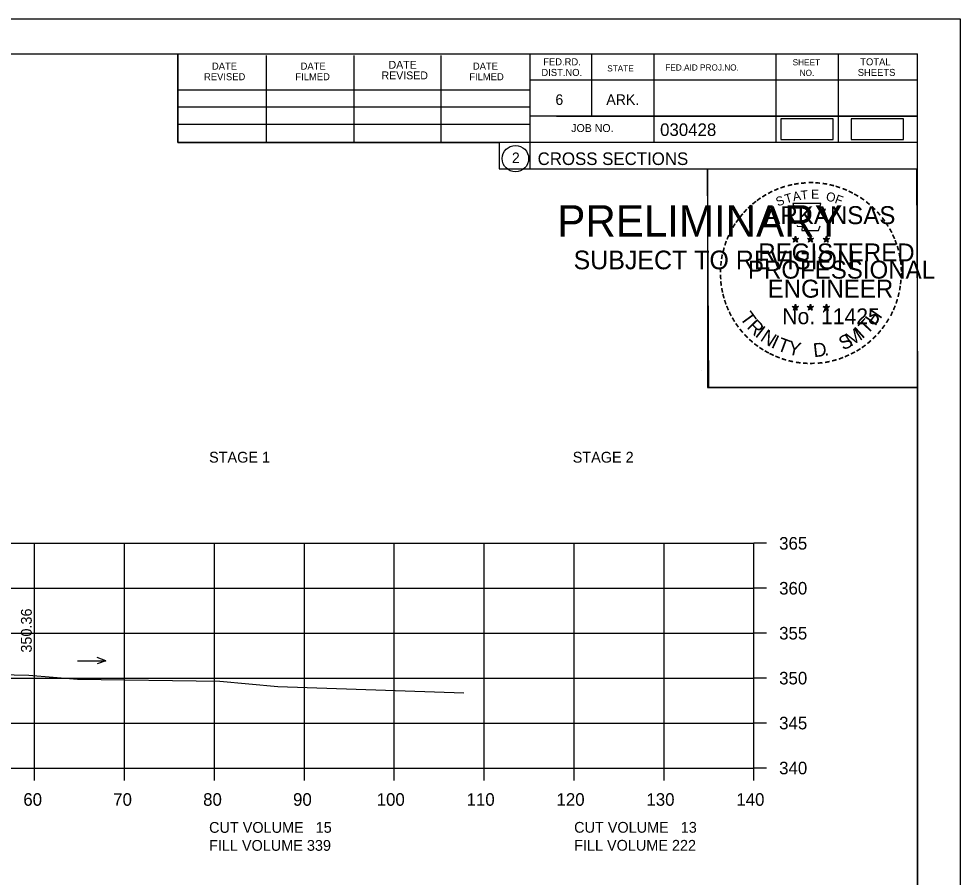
# Model space of a CAD drawing. Extents: x 1374859 to 1376773, y 382242 to 389804.
# Drawn here: x 1376192.8 to 1376297.5, y 382359.6 to 382455.1 of the extents above; entities that cross this region are included whole.
import ezdxf

# ---------------------------------------------------------------- set-up
doc = ezdxf.new("R2010")
doc.units = 0
for name, color, linetype in [('R_Axis', 7, 'Continuous'), ('R_Axis Annot', 7, 'Continuous'), ('R_Border', 7, 'Continuous'), ('R_Border PE', 7, 'Continuous'), ('R_Border Prem', 7, 'Continuous'), ('R_Exist Surface', 7, 'Continuous'), ('R_Grid', 7, 'Continuous'), ('R_MOT', 7, 'Continuous'), ('R_No Plot', 7, 'Continuous'), ('R_Water Annot', 7, 'Continuous'), ('R_Xsect Elev', 7, 'Continuous')]:
    doc.layers.add(name, color=color, linetype=linetype)

msp = doc.modelspace()

# ---------------------------------------------------------------- linework, layer by layer
at = {"layer": 'R_Axis'}
for p, q in [((1376274.57, 382371.72), (1376274.57, 382396.72)), ((1376275.97, 382396.72), (1376274.57, 382396.72)), ((1376275.97, 382391.72), (1376274.57, 382391.72)), ((1376275.97, 382386.72), (1376274.57, 382386.72)), ((1376275.97, 382381.72), (1376274.57, 382381.72)), ((1376275.97, 382376.72), (1376274.57, 382376.72)), ((1375994.57, 382371.72), (1376274.57, 382371.72)), ((1376194.57, 382370.32), (1376194.57, 382371.72)), ((1376204.57, 382370.32), (1376204.57, 382371.72)), ((1376214.57, 382370.32), (1376214.57, 382371.72)), ((1376224.57, 382370.32), (1376224.57, 382371.72)), ((1376234.57, 382370.32), (1376234.57, 382371.72)), ((1376244.57, 382370.32), (1376244.57, 382371.72)), ((1376254.57, 382370.32), (1376254.57, 382371.72)), ((1376264.57, 382370.32), (1376264.57, 382371.72)), ((1376274.57, 382370.32), (1376274.57, 382371.72)), ((1376275.97, 382371.72), (1376274.57, 382371.72))]:
    msp.add_line(p, q, dxfattribs=at)
at = {"layer": 'R_Border'}
for p, q in [((1375976.57, 382451.18), (1376292.75, 382451.18)), ((1376210.49, 382441.3), (1376210.49, 382451.18)), ((1376249.65, 382451.18), (1376249.65, 382438.38)), ((1376256.49, 382451.18), (1376256.49, 382444.24)), ((1376263.43, 382451.18), (1376263.43, 382441.3)), ((1376277.01, 382451.18), (1376277.01, 382441.3)), ((1376283.95, 382451.18), (1376283.95, 382441.3)), ((1376292.75, 382245.72), (1376292.75, 382451.18)), ((1376220.35, 382441.3), (1376220.35, 382450.98)), ((1376230.11, 382441.3), (1376230.11, 382450.98)), ((1376239.79, 382441.3), (1376239.79, 382450.98)), ((1376292.75, 382448.24), (1376249.65, 382448.24)), ((1376292.75, 382448.26), (1376292.75, 382448.26)), ((1376210.49, 382447.16), (1376249.65, 382447.16)), ((1376210.49, 382445.3), (1376249.65, 382445.3)), ((1376292.75, 382444.24), (1376249.65, 382444.24)), ((1376252.61, 382444.24), (1376292.75, 382444.24)), ((1376210.49, 382441.3), (1376210.49, 382443.36)), ((1376210.49, 382443.36), (1376249.65, 382443.36)), ((1376292.75, 382441.3), (1376210.49, 382441.3)), ((1376249.65, 382438.38), (1376292.75, 382438.38))]:
    msp.add_line(p, q, dxfattribs=at)
msp.add_circle((1376248.04, 382439.52), 1.47, dxfattribs=at)
at = {"layer": 'R_Border PE'}
for p, q in [((1376278.84, 382430.64), (1376279.18, 382430.52)), ((1376278.84, 382430.64), (1376279.09, 382430.59)), ((1376278.84, 382430.64), (1376279.07, 382430.51)), ((1376278.97, 382430.23), (1376279.18, 382430.52)), ((1376278.97, 382430.23), (1376279.09, 382430.47)), ((1376278.97, 382430.23), (1376279.18, 382430.44)), ((1376279.18, 382430.89), (1376279.14, 382430.64)), ((1376279.18, 382430.52), (1376279.18, 382430.89)), ((1376279.18, 382430.89), (1376279.23, 382430.64)), ((1376279.53, 382430.64), (1376279.18, 382430.52)), ((1376279.4, 382430.23), (1376279.18, 382430.52)), ((1376279.4, 382430.23), (1376279.18, 382430.44)), ((1376279.53, 382430.64), (1376279.25, 382430.59)), ((1376279.4, 382430.23), (1376279.26, 382430.52)), ((1376279.53, 382430.64), (1376279.33, 382430.53)), ((1376280.51, 382430.64), (1376280.85, 382430.52)), ((1376280.51, 382430.64), (1376280.76, 382430.59)), ((1376280.51, 382430.64), (1376280.74, 382430.51)), ((1376280.64, 382430.23), (1376280.85, 382430.52)), ((1376280.64, 382430.23), (1376280.76, 382430.47)), ((1376280.64, 382430.23), (1376280.85, 382430.44)), ((1376280.85, 382430.89), (1376280.81, 382430.64)), ((1376280.85, 382430.52), (1376280.85, 382430.89)), ((1376280.85, 382430.89), (1376280.9, 382430.64)), ((1376281.2, 382430.64), (1376280.85, 382430.52)), ((1376281.07, 382430.23), (1376280.85, 382430.52)), ((1376281.07, 382430.23), (1376280.85, 382430.44)), ((1376281.2, 382430.64), (1376280.92, 382430.59)), ((1376281.07, 382430.23), (1376280.93, 382430.52)), ((1376281.2, 382430.64), (1376281, 382430.53)), ((1376282.27, 382430.62), (1376282.62, 382430.51)), ((1376282.27, 382430.62), (1376282.52, 382430.58)), ((1376282.27, 382430.62), (1376282.51, 382430.5)), ((1376282.4, 382430.22), (1376282.62, 382430.51)), ((1376282.4, 382430.22), (1376282.53, 382430.46)), ((1376282.4, 382430.22), (1376282.62, 382430.43)), ((1376282.62, 382430.88), (1376282.58, 382430.63)), ((1376282.62, 382430.51), (1376282.62, 382430.88)), ((1376282.62, 382430.88), (1376282.67, 382430.63)), ((1376282.97, 382430.62), (1376282.62, 382430.51)), ((1376282.83, 382430.22), (1376282.62, 382430.51)), ((1376282.83, 382430.22), (1376282.62, 382430.43)), ((1376282.97, 382430.62), (1376282.68, 382430.57)), ((1376282.83, 382430.22), (1376282.69, 382430.51)), ((1376282.97, 382430.62), (1376282.76, 382430.52)), ((1376278.83, 382423.06), (1376279.18, 382422.95)), ((1376278.83, 382423.06), (1376279.08, 382423.02)), ((1376278.83, 382423.06), (1376279.07, 382422.94)), ((1376278.96, 382422.65), (1376279.18, 382422.95)), ((1376278.96, 382422.65), (1376279.09, 382422.9)), ((1376278.96, 382422.65), (1376279.18, 382422.87)), ((1376279.18, 382423.32), (1376279.14, 382423.06)), ((1376279.18, 382422.95), (1376279.18, 382423.32)), ((1376279.18, 382423.32), (1376279.23, 382423.07)), ((1376279.53, 382423.06), (1376279.18, 382422.95)), ((1376279.39, 382422.65), (1376279.18, 382422.95)), ((1376279.39, 382422.65), (1376279.18, 382422.87)), ((1376279.53, 382423.06), (1376279.24, 382423.01)), ((1376279.39, 382422.65), (1376279.26, 382422.95)), ((1376279.53, 382423.06), (1376279.32, 382422.96)), ((1376280.5, 382423.06), (1376280.85, 382422.95)), ((1376280.5, 382423.06), (1376280.75, 382423.02)), ((1376280.5, 382423.06), (1376280.74, 382422.94)), ((1376280.63, 382422.65), (1376280.85, 382422.95)), ((1376280.63, 382422.65), (1376280.76, 382422.9)), ((1376280.63, 382422.65), (1376280.85, 382422.87)), ((1376280.85, 382423.32), (1376280.81, 382423.06)), ((1376280.85, 382422.95), (1376280.85, 382423.32)), ((1376280.85, 382423.32), (1376280.9, 382423.07)), ((1376281.2, 382423.06), (1376280.85, 382422.95)), ((1376281.06, 382422.65), (1376280.85, 382422.95)), ((1376281.06, 382422.65), (1376280.85, 382422.87)), ((1376281.2, 382423.06), (1376280.91, 382423.01)), ((1376281.06, 382422.65), (1376280.93, 382422.95)), ((1376281.2, 382423.06), (1376280.99, 382422.96)), ((1376282.27, 382423.05), (1376282.62, 382422.94)), ((1376282.27, 382423.05), (1376282.52, 382423.01)), ((1376282.27, 382423.05), (1376282.5, 382422.93)), ((1376282.4, 382422.64), (1376282.62, 382422.94)), ((1376282.4, 382422.64), (1376282.53, 382422.89)), ((1376282.4, 382422.64), (1376282.61, 382422.86)), ((1376282.62, 382423.31), (1376282.58, 382423.05)), ((1376282.83, 382422.64), (1376282.61, 382422.86)), ((1376282.62, 382422.94), (1376282.62, 382423.31)), ((1376282.62, 382423.31), (1376282.67, 382423.06)), ((1376282.96, 382423.05), (1376282.62, 382422.94)), ((1376282.83, 382422.64), (1376282.62, 382422.94)), ((1376282.96, 382423.05), (1376282.68, 382423)), ((1376282.83, 382422.64), (1376282.69, 382422.94)), ((1376282.96, 382423.05), (1376282.76, 382422.95))]:
    msp.add_line(p, q, dxfattribs=at)
for points in [[(1376278.88, 382434.51), (1376279.15, 382433.69)], [(1376282.39, 382433.59), (1376282.53, 382433.88), (1376281.84, 382433.85), (1376281.99, 382434.51), (1376278.88, 382434.51)], [(1376279.37, 382432.09), (1376279.37, 382432), (1376279.93, 382431.98), (1376279.88, 382431.51), (1376281.75, 382431.51), (1376281.95, 382432.05)], [(1376279.18, 382430.89), (1376279.4, 382430.23), (1376278.84, 382430.64), (1376279.53, 382430.64), (1376278.97, 382430.23), (1376279.18, 382430.89)], [(1376280.85, 382430.89), (1376281.07, 382430.23), (1376280.51, 382430.64), (1376281.2, 382430.64), (1376280.64, 382430.23), (1376280.85, 382430.89)], [(1376282.62, 382430.88), (1376282.83, 382430.22), (1376282.27, 382430.62), (1376282.97, 382430.62), (1376282.4, 382430.22), (1376282.62, 382430.88)], [(1376279.18, 382423.32), (1376279.39, 382422.65), (1376278.83, 382423.06), (1376279.53, 382423.06), (1376278.96, 382422.65), (1376279.18, 382423.32)], [(1376280.85, 382423.32), (1376281.06, 382422.65), (1376280.5, 382423.06), (1376281.2, 382423.06), (1376280.63, 382422.65), (1376280.85, 382423.32)], [(1376282.62, 382423.31), (1376282.83, 382422.64), (1376282.27, 382423.05), (1376282.96, 382423.05), (1376282.4, 382422.64), (1376282.62, 382423.31)]]:
    msp.add_lwpolyline(points, dxfattribs=at)
for centre, radius in [((1376279.18, 382430.52), 0.172), ((1376279.18, 382430.52), 0.145), ((1376279.18, 382430.52), 0.116), ((1376279.18, 382430.52), 0.0991), ((1376279.18, 382430.52), 0.0747), ((1376279.18, 382430.52), 0.0495), ((1376279.18, 382430.52), 0.0296), ((1376280.85, 382430.52), 0.172), ((1376280.85, 382430.52), 0.145), ((1376280.85, 382430.52), 0.116), ((1376280.85, 382430.52), 0.0991), ((1376280.85, 382430.52), 0.0747), ((1376280.85, 382430.52), 0.0495), ((1376280.85, 382430.52), 0.0296), ((1376282.62, 382430.51), 0.172), ((1376282.62, 382430.51), 0.145), ((1376282.62, 382430.51), 0.116), ((1376282.62, 382430.51), 0.0991), ((1376282.62, 382430.51), 0.0747), ((1376282.62, 382430.51), 0.0495), ((1376282.62, 382430.51), 0.0296), ((1376279.18, 382422.95), 0.172), ((1376279.18, 382422.95), 0.145), ((1376279.18, 382422.95), 0.116), ((1376279.18, 382422.95), 0.0991), ((1376279.18, 382422.95), 0.0747), ((1376279.18, 382422.95), 0.0495), ((1376279.18, 382422.95), 0.0296), ((1376280.85, 382422.95), 0.172), ((1376280.85, 382422.95), 0.145), ((1376280.85, 382422.95), 0.116), ((1376280.85, 382422.95), 0.0991), ((1376280.85, 382422.95), 0.0747), ((1376280.85, 382422.95), 0.0495), ((1376280.85, 382422.95), 0.0296), ((1376282.62, 382422.94), 0.172), ((1376282.62, 382422.94), 0.145), ((1376282.62, 382422.94), 0.116), ((1376282.62, 382422.94), 0.0991), ((1376282.62, 382422.94), 0.0747), ((1376282.62, 382422.94), 0.0495), ((1376282.62, 382422.94), 0.0296)]:
    msp.add_circle(centre, radius, dxfattribs=at)
at = {"layer": 'R_Exist Surface'}
msp.add_lwpolyline([(1376074.07, 382383.65), (1376082.2, 382383.68), (1376083.35, 382383.71), (1376093.58, 382383.15), (1376102.46, 382386.11), (1376105.38, 382387.13), (1376115.82, 382390.6), (1376117.69, 382390.67), (1376123.23, 382390.89), (1376129.54, 382391.04), (1376135.35, 382391.19), (1376141.62, 382391), (1376147.42, 382390.82), (1376152.27, 382390.54), (1376157.14, 382390.2), (1376162.27, 382388.39), (1376169.25, 382385.85), (1376180.89, 382382.3), (1376184.16, 382382.26), (1376193.92, 382382.05), (1376199.35, 382381.62), (1376215.18, 382381.38), (1376221.62, 382380.78), (1376242.32, 382380.08)], dxfattribs=at)
at = {"layer": 'R_Grid'}
for p, q in [((1375994.57, 382396.72), (1376274.57, 382396.72)), ((1376194.57, 382371.72), (1376194.57, 382396.72)), ((1376204.57, 382371.72), (1376204.57, 382396.72)), ((1376214.57, 382371.72), (1376214.57, 382396.72)), ((1376224.57, 382371.72), (1376224.57, 382396.72)), ((1376234.57, 382371.72), (1376234.57, 382396.72)), ((1376244.57, 382371.72), (1376244.57, 382396.72)), ((1376254.57, 382371.72), (1376254.57, 382396.72)), ((1376264.57, 382371.72), (1376264.57, 382396.72)), ((1376274.57, 382371.72), (1376274.57, 382396.72)), ((1375994.57, 382391.72), (1376274.57, 382391.72)), ((1375994.57, 382386.72), (1376274.57, 382386.72)), ((1375994.57, 382381.72), (1376274.57, 382381.72)), ((1375994.57, 382376.72), (1376274.57, 382376.72)), ((1375994.57, 382371.72), (1376274.57, 382371.72))]:
    msp.add_line(p, q, dxfattribs=at)
at = {"layer": 'R_MOT'}
for points in [[(1376277.55, 382441.65), (1376283.38, 382441.65), (1376283.38, 382443.96), (1376277.55, 382443.96)], [(1376285.38, 382441.65), (1376291.21, 382441.65), (1376291.21, 382443.96), (1376285.38, 382443.96)]]:
    msp.add_lwpolyline(points, close=True, dxfattribs=at)
at = {"layer": 'R_No Plot'}
for p, q in [((1375964.17, 382455.07), (1376297.5, 382455.07)), ((1376268.78, 382415.92), (1376268.78, 382415.92))]:
    msp.add_line(p, q, dxfattribs=at)
for points in [[(1375964.16, 382455.07), (1376297.5, 382455.07), (1376297.5, 382241.74), (1375964.16, 382241.74)], [(1376210.49, 382451.18), (1376210.49, 382441.3), (1376246.22, 382441.3), (1376246.22, 382438.38), (1376269.42, 382438.38), (1376269.42, 382414.05), (1376292.75, 382414.05), (1376292.75, 382245.72), (1375976.57, 382245.72), (1375976.57, 382451.18)], [(1376269.42, 382438.38), (1376292.63, 382438.38), (1376292.75, 382414.05), (1376269.54, 382414.05)]]:
    msp.add_lwpolyline(points, close=True, dxfattribs=at)
at = {"layer": 'R_Water Annot'}
for p, q in [((1376199.35, 382383.65), (1376202.49, 382383.65)), ((1376202.49, 382383.65), (1376201.53, 382384)), ((1376202.49, 382383.65), (1376201.53, 382383.3))]:
    msp.add_line(p, q, dxfattribs=at)

# ---------------------------------------------------------------- texts
at = {"layer": 'R_Axis Annot'}
for s, p in [('STAGE 1', (1376213.97, 382405.7)), ('STAGE 2', (1376254.41, 382405.7))]:
    msp.add_text(s, height=1.2, rotation=360, dxfattribs=at).set_placement(p)
for s, height, p in [('365', 1.4, (1376277.37, 382396.02)), ('360', 1.4, (1376277.37, 382391.02)), ('355', 1.4, (1376277.37, 382386.02)), ('350', 1.4, (1376277.37, 382381.02)), ('345', 1.4, (1376277.37, 382376.02)), ('340', 1.4, (1376277.37, 382371.02)), ('60', 1.4, (1376193.31, 382367.52)), ('70', 1.4, (1376203.31, 382367.52)), ('80', 1.4, (1376213.31, 382367.52)), ('90', 1.4, (1376223.31, 382367.52)), ('100', 1.4, (1376232.61, 382367.52)), ('110', 1.4, (1376242.61, 382367.52)), ('120', 1.4, (1376252.61, 382367.52)), ('130', 1.4, (1376262.61, 382367.52)), ('140', 1.4, (1376272.61, 382367.52)), ('CUT VOLUME   15', 1.2, (1376213.97, 382364.51)), ('CUT VOLUME   13', 1.2, (1376254.57, 382364.52)), ('FILL VOLUME 339', 1.2, (1376213.97, 382362.51)), ('FILL VOLUME 222', 1.2, (1376254.57, 382362.52))]:
    msp.add_text(s, height=height, dxfattribs=at).set_placement(p)
at = {"layer": 'R_Border'}
for s, height, p in [('DATE', 0.782, (1376214.29, 382449.42)), ('DATE', 0.782, (1376224.15, 382449.42)), ('DATE', 0.879, (1376233.93, 382449.52)), ('DATE', 0.782, (1376243.31, 382449.42)), ('FED.RD.', 0.782, (1376251.13, 382449.9)), ('SHEET', 0.684, (1376278.87, 382449.9)), ('TOTAL', 0.782, (1376286.39, 382449.9)), ('REVISED', 0.782, (1376213.41, 382448.24)), ('FILMED', 0.782, (1376223.57, 382448.24)), ('REVISED', 0.879, (1376233.15, 382448.34)), ('FILMED', 0.782, (1376242.91, 382448.24)), ('DIST.NO.', 0.782, (1376250.93, 382448.72)), ('STATE', 0.684, (1376258.25, 382449.22)), ('FED.AID PROJ.NO.', 0.684, (1376264.71, 382449.32)), ('NO.', 0.684, (1376279.65, 382448.72)), ('SHEETS', 0.782, (1376286.11, 382448.72)), ('6', 1.17, (1376252.49, 382445.5)), ('ARK.', 1.172, (1376258.15, 382445.5)), ('JOB NO.', 0.879, (1376254.25, 382442.48)), ('030428', 1.4, (1376264.13, 382442.04)), ('2', 1.17, (1376247.65, 382439.03)), ('CROSS SECTIONS', 1.4, (1376250.51, 382438.81))]:
    msp.add_text(s, height=height, rotation=360, dxfattribs=at).set_placement(p)
at = {"layer": 'R_Border PE'}
for s, height, rotation, p in [('-', 1.6, 19.1761, (1376277.62, 382435.64)), ('-', 1.6, 13.6301, (1376278.37, 382435.88)), ('-', 1.6, 10.2193, (1376279.05, 382436.04)), ('-', 1.6, 5.8968, (1376279.78, 382436.15)), ('-', 1.6, 0.1862, (1376280.55, 382436.23)), ('-', 1.6, 357.743, (1376281.28, 382436.21)), ('-', 1.6, 352.1617, (1376282.02, 382436.16)), ('-', 1.6, 347.2049, (1376282.74, 382436.04)), ('-', 1.6, 342.3362, (1376283.37, 382435.89)), ('-', 1.6, 34.0636, (1376275.76, 382434.68)), ('-', 1.6, 28.7918, (1376276.36, 382435.05)), ('-', 1.6, 24.3072, (1376276.99, 382435.37)), ('T', 1, 16.4036, (1376278.15, 382434.52)), ('A', 1, 11.2132, (1376278.97, 382434.77)), ('T', 1, 6.0228, (1376279.82, 382434.94)), ('E', 1, 0.8323, (1376280.93, 382435.05)), ('O', 1, 350.4515, (1376282.53, 382434.84)), ('F', 1, 340.0707, (1376283.48, 382434.61)), ('-', 1.6, 337.8551, (1376284.11, 382435.66)), ('-', 1.6, 334.1211, (1376284.74, 382435.39)), ('-', 1.6, 329.6409, (1376285.32, 382435.11)), ('-', 1.6, 42.9622, (1376274.27, 382433.49)), ('-', 1.6, 38.9507, (1376274.71, 382433.91)), ('-', 1.6, 36.2317, (1376275.18, 382434.29)), ('S', 1, 21.594, (1376277.23, 382434.19)), ('-', 1.6, 325.8627, (1376285.96, 382434.75)), ('-', 1.6, 320.5297, (1376286.57, 382434.32)), ('-', 1.6, 50.6142, (1376273.42, 382432.53)), ('-', 1.6, 48.423, (1376273.83, 382433.02)), ('ARKANSAS', 2, 360, (1376275.73, 382432.23)), ('-', 1.6, 315.5786, (1376287.17, 382433.84)), ('-', 1.6, 309.8797, (1376287.74, 382433.29)), ('-', 1.6, 58.0706, (1376272.68, 382431.44)), ('-', 1.6, 54.2325, (1376273.01, 382431.96)), ('-', 1.6, 306.6522, (1376288.27, 382432.68)), ('-', 1.4, 303.6753, (1376288.75, 382432.12)), ('-', 1.6, 62.8713, (1376272.37, 382430.82)), ('-', 1.6, 299.6684, (1376289.07, 382431.51)), ('-', 1.6, 72.3945, (1376271.89, 382429.58)), ('-', 1.6, 67.7743, (1376272.11, 382430.21)), ('DWB', 0.01, 360, (1376279.17, 382430.52)), ('DWB', 0.01, 360, (1376280.84, 382430.52)), ('DWB', 0.01, 360, (1376282.61, 382430.51)), ('-', 1.6, 294.6628, (1376289.39, 382430.9)), ('-', 1.6, 290.5728, (1376289.65, 382430.32)), ('-', 1.6, 75.461, (1376271.7, 382428.87)), ('REGISTERED', 2, 360, (1376275.05, 382428.08)), ('-', 1.6, 285.1233, (1376289.89, 382429.74)), ('-', 1.6, 85.1863, (1376271.49, 382427.46)), ('-', 1.6, 81.2013, (1376271.56, 382428.15)), ('PROFESSIONAL', 2, 360, (1376273.9, 382426.17)), ('-', 1.6, 280.5493, (1376290.09, 382429)), ('-', 1.6, 276.5962, (1376290.25, 382428.23)), ('-', 1.6, 89.0622, (1376271.46, 382426.76)), ('-', 1.6, 274.3301, (1376290.31, 382427.51)), ('-', 1.6, 94.1959, (1376271.5, 382426.04)), ('ENGINEER', 2, 360, (1376276.09, 382424.05)), ('-', 1.6, 263.5172, (1376290.32, 382426.21)), ('-', 1.6, 269.9407, (1376290.34, 382426.88)), ('-', 1.6, 98.9479, (1376271.57, 382425.37)), ('-', 1.6, 101.7149, (1376271.71, 382424.64)), ('-', 1.6, 260.9953, (1376290.25, 382425.56)), ('-', 1.6, 105.4578, (1376271.87, 382424.04)), ('-', 1.6, 252.8681, (1376289.96, 382424.16)), ('-', 1.6, 255.7626, (1376290.14, 382424.88)), ('-', 1.6, 109.0874, (1376272.08, 382423.41)), ('-', 1.6, 114.0643, (1376272.34, 382422.82)), ('No. 11425', 1.757, 360, (1376277.72, 382421.1)), ('DWB', 0.01, 360, (1376279.17, 382422.95)), ('DWB', 0.01, 360, (1376280.84, 382422.95)), ('DWB', 0.01, 360, (1376282.6, 382422.94)), ('-', 1.6, 247.8887, (1376289.74, 382423.48)), ('-', 1.6, 115.7289, (1376272.64, 382422.2)), ('-', 1.6, 120.4471, (1376273, 382421.61)), ('T', 1.54, 306.0406, (1376272.94, 382421.79)), ('T', 1.54, 46.6444, (1376287.17, 382419.88)), ('H', 1.54, 54.6088, (1376288.06, 382420.82)), ('-', 1.6, 244.6197, (1376289.48, 382422.86)), ('-', 1.6, 125.8934, (1376273.4, 382421.05)), ('R', 1.54, 314.005, (1376273.7, 382420.74)), ('I', 1.54, 321.9694, (1376274.6, 382419.81)), ('I', 1.54, 42.1136, (1376286.61, 382419.4)), ('-', 1.6, 233.8452, (1376288.68, 382421.45)), ('-', 1.6, 239.0712, (1376289.08, 382422.1)), ('-', 1.6, 130.7181, (1376273.86, 382420.5)), ('-', 1.6, 134.2238, (1376274.38, 382419.95)), ('N', 1.54, 326.5002, (1376275.17, 382419.34)), ('I', 1.54, 335.3603, (1376276.38, 382418.55)), ('S', 1.54, 26.9312, (1376284.49, 382418.15)), ('M', 1.54, 32.6563, (1376285.32, 382418.56)), ('-', 1.6, 225.7653, (1376287.77, 382420.32)), ('-', 1.6, 231.2538, (1376288.25, 382420.88)), ('-', 1.6, 138.9338, (1376274.91, 382419.49)), ('-', 1.6, 144.6463, (1376275.46, 382419.08)), ('T', 1.54, 339.8912, (1376277.04, 382418.22)), ('Y', 1.54, 347.8556, (1376278.26, 382417.78)), ('D', 1.54, 6.3969, (1376281.24, 382417.42)), ('-', 1.6, 215.7363, (1376286.7, 382419.34)), ('-', 1.6, 221.0851, (1376287.25, 382419.81)), ('-', 1.6, 148.0898, (1376276.02, 382418.71)), ('-', 1.6, 151.5704, (1376276.6, 382418.39)), ('-', 1.6, 154.6002, (1376277.12, 382418.14)), ('-', 1.6, 158.5612, (1376277.75, 382417.89)), ('.', 1.54, 13.7642, (1376282.43, 382417.55)), ('-', 1.6, 204.2516, (1376284.98, 382418.29)), ('-', 1.6, 207.3568, (1376285.61, 382418.61)), ('-', 1.6, 212.2491, (1376286.17, 382418.95)), ('-', 1.6, 162.7983, (1376278.43, 382417.67)), ('-', 1.6, 167.5555, (1376279.15, 382417.51)), ('-', 1.6, 173.1155, (1376279.92, 382417.4)), ('-', 1.6, 176.5183, (1376280.67, 382417.35)), ('-', 1.6, 181.5918, (1376281.41, 382417.37)), ('-', 1.6, 185.8167, (1376282.22, 382417.44)), ('-', 1.6, 191.2858, (1376282.96, 382417.57)), ('-', 1.6, 195.4743, (1376283.69, 382417.77)), ('-', 1.6, 200.7184, (1376284.36, 382418.01))]:
    msp.add_text(s, height=height, rotation=rotation, dxfattribs=at).set_placement(p)
at = {"layer": 'R_Border Prem'}
for s, height, p in [('PRELIMINARY', 3.5, (1376252.7, 382430.84)), ('DWB', 0.01, (1376253.45, 382432.69)), ('SUBJECT TO REVISION', 2.0751, (1376254.51, 382427.21))]:
    msp.add_text(s, height=height, rotation=360, dxfattribs=at).set_placement(p)
at = {"layer": 'R_Xsect Elev'}
msp.add_text('350.36', height=1.2, rotation=90, dxfattribs=at).set_placement((1376194.25, 382384.56))

doc.saveas('drawing.dxf')
